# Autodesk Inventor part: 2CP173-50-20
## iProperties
Created: 2007-02
Part Number: 2CP173-50-20
Document SubType Name: Modeling
Designer: Darius
Author: Darius
Title: 2CP173-50-20
Subject: Connecting Plate
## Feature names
1. Extrusion1
2. Hole1
3. Hole2
4. Hole3
